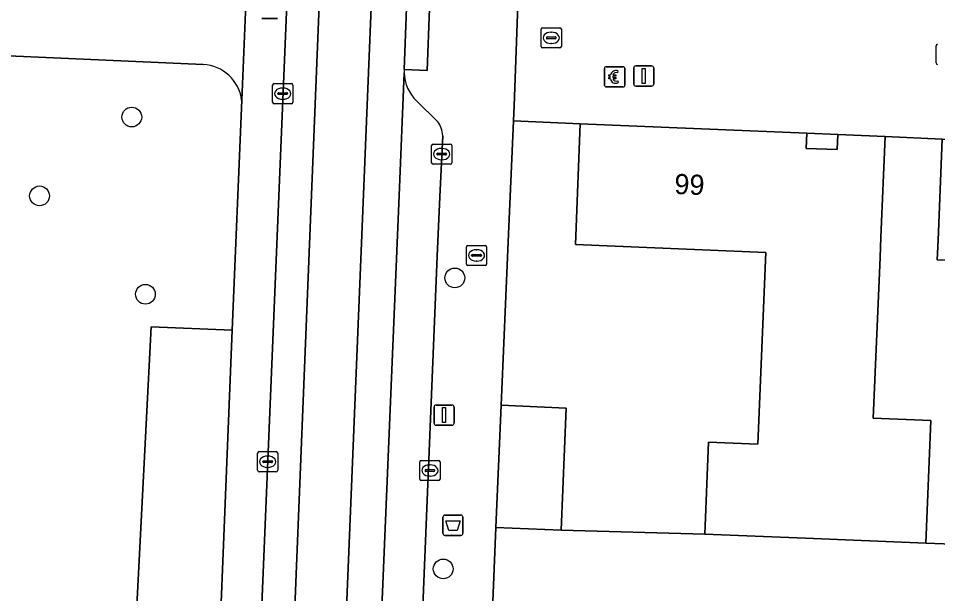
# Model space of a CAD drawing. Extents: x 160786 to 161429, y 386828 to 387485.
# Drawn here: x 161279.33 to 161324.86, y 386925.96 to 386954.48 of the extents above; entities that cross this region are included whole.
import ezdxf

# ---------------------------------------------------------------- set-up
doc = ezdxf.new("R2010")
doc.units = 0
for name, color, linetype in [('IMGEO_Afvalbak', 7, 'Continuous'), ('IMGEO_Betaalautomaat', 7, 'Continuous'), ('IMGEO_Boom', 7, 'Continuous'), ('IMGEO_Brandkraan', 7, 'Continuous'), ('IMGEO_Erf', 7, 'Continuous'), ('IMGEO_Groenvoorziening', 7, 'Continuous'), ('IMGEO_Hek', 7, 'Continuous'), ('IMGEO_Kolk', 7, 'Continuous'), ('IMGEO_Lichtmast', 7, 'Continuous'), ('IMGEO_Muur', 7, 'Continuous'), ('IMGEO_Pand', 7, 'Continuous'), ('IMGEO_Pand_nummerreeks', 7, 'Continuous'), ('IMGEO_Parkeervlak_gesloten', 7, 'Continuous'), ('IMGEO_Rijbaan_lokaal_gesloten', 7, 'Continuous'), ('IMGEO_Rijbaan_lokaal_open', 7, 'Continuous'), ('IMGEO_Voetpad_open', 7, 'Continuous')]:
    doc.layers.add(name, color=color, linetype=linetype)

msp = doc.modelspace()

# ---------------------------------------------------------------- linework, layer by layer
at = {"layer": 'IMGEO_Afvalbak'}
for p, q in [((161300.455, 386929.852), (161301.245, 386929.852)), ((161301.245, 386929.852), (161300.455, 386929.852)), ((161300.355, 386928.952), (161300.355, 386929.752)), ((161300.355, 386929.752), (161300.355, 386928.952)), ((161301.345, 386929.752), (161301.345, 386928.952)), ((161301.345, 386928.952), (161301.345, 386929.752)), ((161301.245, 386928.852), (161300.455, 386928.852)), ((161300.455, 386928.852), (161301.245, 386928.852))]:
    msp.add_line(p, q, dxfattribs=at)
msp.add_lwpolyline([(161300.498, 386929.566), (161301.202, 386929.566), (161301.053, 386929.096), (161300.647, 386929.096), (161300.498, 386929.566)], dxfattribs=at)
for centre, start, end in [((161300.455, 386929.752), 90, 180), ((161300.455, 386929.752), 90, 180), ((161301.245, 386929.752), 0, 90), ((161301.245, 386929.752), 360, 90), ((161300.455, 386928.952), 180, 270), ((161300.455, 386928.952), 180, 270), ((161301.245, 386928.952), 270, 0), ((161301.245, 386928.952), 270, 0)]:
    msp.add_arc(centre, 0.1, start, end, dxfattribs=at)
at = {"layer": 'IMGEO_Betaalautomaat'}
for p, q in [((161308.362, 386951.154), (161308.362, 386951.995)), ((161308.362, 386951.995), (161308.362, 386951.154)), ((161308.437, 386952.078), (161309.278, 386952.078)), ((161309.278, 386952.078), (161308.437, 386952.078)), ((161309.024, 386951.883), (161309.007, 386951.783)), ((161309.361, 386952.004), (161309.361, 386951.163)), ((161309.361, 386951.163), (161309.361, 386952.004)), ((161308.645, 386951.542), (161308.645, 386951.61)), ((161308.766, 386951.61), (161308.766, 386951.542)), ((161309.011, 386951.377), (161309.033, 386951.29)), ((161309.287, 386951.079), (161308.446, 386951.079)), ((161308.446, 386951.079), (161309.287, 386951.079))]:
    msp.add_line(p, q, dxfattribs=at)
for points in [[(161308.645, 386951.61), (161308.576, 386951.61), (161308.576, 386951.679), (161308.655, 386951.679)], [(161308.65, 386951.473), (161308.576, 386951.473), (161308.576, 386951.542), (161308.645, 386951.542)], [(161308.777, 386951.679), (161308.924, 386951.679), (161308.924, 386951.61), (161308.766, 386951.61)], [(161308.766, 386951.542), (161308.924, 386951.542), (161308.924, 386951.473), (161308.78, 386951.473)]]:
    msp.add_lwpolyline(points, dxfattribs=at)
for centre, radius, start, end in [((161308.44, 386952.001), 0.0779, 92.4484, 184.2845), ((161308.44, 386952.001), 0.0779, 92.4484, 184.2845), ((161308.938, 386951.603), 0.293, 73.014, 165.0139), ((161308.944, 386951.616), 0.179, 69.3236, 159.5683), ((161309.284, 386952.001), 0.0779, 2.4484, 94.2845), ((161309.284, 386952.001), 0.0779, 2.4484, 94.2845), ((161308.911, 386951.528), 0.267, 191.8096, 297.0389), ((161308.944, 386951.543), 0.179, 202.7625, 291.8693), ((161308.44, 386951.157), 0.0779, 182.4484, 274.2845), ((161308.44, 386951.157), 0.0779, 182.4484, 274.2845), ((161309.284, 386951.157), 0.0779, 272.4484, 4.2845), ((161309.284, 386951.157), 0.0779, 272.4484, 4.2845)]:
    msp.add_arc(centre, radius, start, end, dxfattribs=at)
at = {"layer": 'IMGEO_Boom'}
for centre in [(161284.944, 386949.587), (161280.373, 386945.679), (161300.945, 386941.612), (161285.619, 386940.8), (161300.368, 386927.189)]:
    msp.add_circle(centre, 0.489, dxfattribs=at)
at = {"layer": 'IMGEO_Brandkraan'}
for p, q in [((161301.519, 386942.3), (161301.519, 386943.152)), ((161301.594, 386943.226), (161302.446, 386943.226)), ((161302.52, 386943.152), (161302.52, 386942.3)), ((161301.778, 386942.72), (161301.778, 386942.732)), ((161302.216, 386942.683), (161301.818, 386942.683)), ((161301.821, 386942.769), (161302.219, 386942.769)), ((161302.007, 386943.006), (161302.032, 386943.006)), ((161302.262, 386942.732), (161302.262, 386942.72)), ((161302.446, 386942.226), (161301.594, 386942.226)), ((161302.03, 386942.446), (161302.005, 386942.446))]:
    msp.add_line(p, q, dxfattribs=at)
for points in [[(161301.519, 386942.3), (161301.519, 386943.152)], [(161301.594, 386943.226), (161302.446, 386943.226)], [(161302.52, 386943.152), (161302.52, 386942.3)], [(161302.446, 386942.226), (161301.594, 386942.226)]]:
    msp.add_lwpolyline(points, dxfattribs=at)
for centre, radius, start, end in [((161301.596, 386943.15), 0.0765, 91.552, 178.448), ((161301.596, 386943.15), 0.0765, 91.552, 178.448), ((161302.444, 386943.15), 0.0765, 1.552, 88.448), ((161302.444, 386943.15), 0.0765, 1.552, 88.448), ((161301.818, 386942.729), 0.0403, 85.8775, 175.7526), ((161301.815, 386942.719), 0.0366, 178.938, 274.7102), ((161302.219, 386942.726), 0.043, 264.8664, 352.4533), ((161302.223, 386942.731), 0.0386, 1.7309, 96.639), ((161301.596, 386942.302), 0.0765, 181.552, 268.448), ((161301.596, 386942.302), 0.0765, 181.552, 268.448), ((161302.444, 386942.302), 0.0765, 271.552, 358.448), ((161302.444, 386942.302), 0.0765, 271.552, 358.448)]:
    msp.add_arc(centre, radius, start, end, dxfattribs=at)
for centre, major_axis, ratio, start_param, end_param in [((161302.006, 386942.726), (-0.387, 0.002), 0.722429, 4.712389, 7.853982), ((161302.031, 386942.726), (-0.39, 0.002), 0.717154, 1.570796, 4.712389)]:
    msp.add_ellipse(centre, major_axis=major_axis, ratio=ratio, start_param=start_param, end_param=end_param, dxfattribs=at)
at = {"layer": 'IMGEO_Erf'}
for points in [[(161303.238, 386935.299), (161306.461, 386935.163), (161306.205, 386929.1), (161313.324, 386928.917), (161313.516, 386933.478), (161315.949, 386933.376), (161316.348, 386942.867), (161306.923, 386943.264), (161307.152, 386949.254), (161303.85, 386949.393), (161303.59, 386943.404)], [(161318.382, 386948.782), (161318.351, 386948.033), (161319.89, 386947.969), (161319.921, 386948.717)], [(161334.304, 386942.104), (161324.836, 386942.502), (161324.878, 386943.488), (161325.088, 386948.483), (161322.258, 386948.619), (161322.048, 386943.624), (161322.006, 386942.621), (161321.671, 386934.657), (161324.526, 386934.537), (161324.27, 386928.456), (161331.342, 386928.203), (161331.53, 386932.684), (161333.904, 386932.585)]]:
    msp.add_lwpolyline(points, close=True, dxfattribs=at)
at = {"layer": 'IMGEO_Groenvoorziening'}
for points in [[(161288.483, 386952.19), (161278.829, 386952.625), (161256.507, 386953.514), (161239.952, 386954.165), (161238.005, 386908.916), (161247.035, 386908.53), (161246.861, 386904.602), (161249.934, 386904.471), (161250.1, 386908.393), (161276.354, 386907.664), (161284.67, 386915.068), (161285.895, 386939.183)], [(161285.895, 386939.183), (161289.921, 386939.02), (161290.386, 386950.426)]]:
    msp.add_lwpolyline(points, dxfattribs=at)
for points in [[(161288.941, 386914.885), (161289.921, 386939.02), (161285.895, 386939.183), (161284.67, 386915.068)], [(161375.253, 386926.43), (161370.258, 386926.64), (161367.184, 386926.77), (161360.13, 386926.991), (161349.258, 386927.448), (161342.263, 386927.744), (161331.342, 386928.203), (161324.27, 386928.456), (161318.32, 386928.707), (161313.324, 386928.917), (161306.205, 386929.1), (161302.982, 386929.236), (161302.493, 386917.433), (161315.258, 386916.897), (161315.473, 386922.033), (161318.102, 386921.923), (161320.34, 386921.824), (161375.065, 386919.394)]]:
    msp.add_lwpolyline(points, close=True, dxfattribs=at)
msp.add_arc((161288.386, 386950.177), 2.015, 7.0993, 87.2423, dxfattribs=at)
at = {"layer": 'IMGEO_Hek'}
msp.add_lwpolyline([(161284.67, 386915.068), (161285.895, 386939.183)], dxfattribs=at)
at = {"layer": 'IMGEO_Kolk'}
for p, q in [((161305.295, 386954.012), (161306.147, 386954.012)), ((161305.22, 386953.086), (161305.22, 386953.938)), ((161305.479, 386953.506), (161305.479, 386953.518)), ((161305.522, 386953.555), (161305.92, 386953.555)), ((161305.708, 386953.792), (161305.733, 386953.792)), ((161305.963, 386953.518), (161305.963, 386953.506)), ((161306.221, 386953.938), (161306.221, 386953.086)), ((161305.917, 386953.469), (161305.519, 386953.469)), ((161305.731, 386953.232), (161305.706, 386953.232)), ((161324.784, 386952.265), (161324.784, 386953.117)), ((161306.147, 386953.012), (161305.295, 386953.012)), ((161291.994, 386951.245), (161292.846, 386951.245)), ((161291.919, 386950.319), (161291.919, 386951.171)), ((161292.221, 386950.788), (161292.619, 386950.788)), ((161292.407, 386951.025), (161292.432, 386951.025)), ((161292.92, 386951.171), (161292.92, 386950.319)), ((161292.178, 386950.739), (161292.178, 386950.751)), ((161292.616, 386950.702), (161292.218, 386950.702)), ((161292.43, 386950.465), (161292.405, 386950.465)), ((161292.662, 386950.751), (161292.662, 386950.739)), ((161292.846, 386950.245), (161291.994, 386950.245)), ((161299.793, 386947.322), (161299.793, 386948.174)), ((161299.868, 386948.248), (161300.72, 386948.248)), ((161300.794, 386948.174), (161300.794, 386947.322)), ((161300.052, 386947.742), (161300.052, 386947.754)), ((161300.49, 386947.705), (161300.092, 386947.705)), ((161300.095, 386947.791), (161300.493, 386947.791)), ((161300.281, 386948.028), (161300.306, 386948.028)), ((161300.536, 386947.754), (161300.536, 386947.742)), ((161300.72, 386947.248), (161299.868, 386947.248)), ((161300.304, 386947.468), (161300.279, 386947.468)), ((161291.173, 386932.076), (161291.173, 386932.928)), ((161291.248, 386933.002), (161292.1, 386933.002)), ((161291.661, 386932.782), (161291.686, 386932.782)), ((161292.174, 386932.928), (161292.174, 386932.076)), ((161299.285, 386932.565), (161300.137, 386932.565)), ((161291.432, 386932.496), (161291.432, 386932.508)), ((161291.87, 386932.459), (161291.472, 386932.459)), ((161291.475, 386932.545), (161291.873, 386932.545)), ((161291.684, 386932.222), (161291.659, 386932.222)), ((161291.916, 386932.508), (161291.916, 386932.496)), ((161299.21, 386931.639), (161299.21, 386932.491)), ((161299.698, 386932.345), (161299.723, 386932.345)), ((161300.211, 386932.491), (161300.211, 386931.639)), ((161292.1, 386932.002), (161291.248, 386932.002)), ((161299.469, 386932.059), (161299.469, 386932.071)), ((161299.907, 386932.022), (161299.509, 386932.022)), ((161299.512, 386932.108), (161299.91, 386932.108)), ((161299.721, 386931.785), (161299.696, 386931.785)), ((161299.953, 386932.071), (161299.953, 386932.059)), ((161300.137, 386931.565), (161299.285, 386931.565))]:
    msp.add_line(p, q, dxfattribs=at)
for points in [[(161305.295, 386954.012), (161306.147, 386954.012)], [(161305.22, 386953.086), (161305.22, 386953.938)], [(161306.221, 386953.938), (161306.221, 386953.086)], [(161324.784, 386952.265), (161324.784, 386953.117)], [(161306.147, 386953.012), (161305.295, 386953.012)], [(161291.994, 386951.245), (161292.846, 386951.245)], [(161291.919, 386950.319), (161291.919, 386951.171)], [(161292.92, 386951.171), (161292.92, 386950.319)], [(161292.846, 386950.245), (161291.994, 386950.245)], [(161299.793, 386947.322), (161299.793, 386948.174)], [(161299.868, 386948.248), (161300.72, 386948.248)], [(161300.794, 386948.174), (161300.794, 386947.322)], [(161300.72, 386947.248), (161299.868, 386947.248)], [(161291.173, 386932.076), (161291.173, 386932.928)], [(161291.248, 386933.002), (161292.1, 386933.002)], [(161292.174, 386932.928), (161292.174, 386932.076)], [(161299.285, 386932.565), (161300.137, 386932.565)], [(161299.21, 386931.639), (161299.21, 386932.491)], [(161300.211, 386932.491), (161300.211, 386931.639)], [(161292.1, 386932.002), (161291.248, 386932.002)], [(161300.137, 386931.565), (161299.285, 386931.565)]]:
    msp.add_lwpolyline(points, dxfattribs=at)
for centre, radius, start, end in [((161305.297, 386953.936), 0.0765, 91.552, 178.448), ((161305.297, 386953.936), 0.0765, 91.552, 178.448), ((161306.145, 386953.936), 0.0765, 1.552, 88.448), ((161306.145, 386953.936), 0.0765, 1.552, 88.448), ((161305.519, 386953.515), 0.0403, 85.8775, 175.7526), ((161305.924, 386953.517), 0.0386, 1.7309, 96.639), ((161305.297, 386953.088), 0.0765, 181.552, 268.448), ((161305.297, 386953.088), 0.0765, 181.552, 268.448), ((161305.516, 386953.505), 0.0366, 178.938, 274.7102), ((161305.92, 386953.512), 0.043, 264.8664, 352.4533), ((161306.145, 386953.088), 0.0765, 271.552, 358.448), ((161306.145, 386953.088), 0.0765, 271.552, 358.448), ((161324.861, 386953.115), 0.0765, 91.552, 178.448), ((161324.861, 386953.115), 0.0765, 91.552, 178.448), ((161324.861, 386952.267), 0.0765, 181.552, 268.448), ((161324.861, 386952.267), 0.0765, 181.552, 268.448), ((161291.996, 386951.169), 0.0765, 91.552, 178.448), ((161291.996, 386951.169), 0.0765, 91.552, 178.448), ((161292.844, 386951.169), 0.0765, 1.552, 88.448), ((161292.844, 386951.169), 0.0765, 1.552, 88.448), ((161292.218, 386950.748), 0.0403, 85.8775, 175.7526), ((161292.623, 386950.75), 0.0386, 1.7309, 96.639), ((161292.215, 386950.738), 0.0366, 178.938, 274.7102), ((161292.619, 386950.745), 0.043, 264.8664, 352.4533), ((161291.996, 386950.321), 0.0765, 181.552, 268.448), ((161291.996, 386950.321), 0.0765, 181.552, 268.448), ((161292.844, 386950.321), 0.0765, 271.552, 358.448), ((161292.844, 386950.321), 0.0765, 271.552, 358.448), ((161299.87, 386948.172), 0.0765, 91.552, 178.448), ((161299.87, 386948.172), 0.0765, 91.552, 178.448), ((161300.718, 386948.172), 0.0765, 1.552, 88.448), ((161300.718, 386948.172), 0.0765, 1.552, 88.448), ((161300.092, 386947.751), 0.0403, 85.8775, 175.7526), ((161300.089, 386947.741), 0.0366, 178.938, 274.7102), ((161300.493, 386947.748), 0.043, 264.8664, 352.4533), ((161300.497, 386947.753), 0.0386, 1.7309, 96.639), ((161299.87, 386947.324), 0.0765, 181.552, 268.448), ((161299.87, 386947.324), 0.0765, 181.552, 268.448), ((161300.718, 386947.324), 0.0765, 271.552, 358.448), ((161300.718, 386947.324), 0.0765, 271.552, 358.448), ((161291.25, 386932.926), 0.0765, 91.552, 178.448), ((161291.25, 386932.926), 0.0765, 91.552, 178.448), ((161292.098, 386932.926), 0.0765, 1.552, 88.448), ((161292.098, 386932.926), 0.0765, 1.552, 88.448), ((161299.287, 386932.489), 0.0765, 91.552, 178.448), ((161299.287, 386932.489), 0.0765, 91.552, 178.448), ((161300.135, 386932.489), 0.0765, 1.552, 88.448), ((161300.135, 386932.489), 0.0765, 1.552, 88.448), ((161291.472, 386932.505), 0.0403, 85.8775, 175.7526), ((161291.469, 386932.495), 0.0366, 178.938, 274.7102), ((161291.873, 386932.502), 0.043, 264.8664, 352.4533), ((161291.877, 386932.507), 0.0386, 1.7309, 96.639), ((161291.25, 386932.078), 0.0765, 181.552, 268.448), ((161291.25, 386932.078), 0.0765, 181.552, 268.448), ((161292.098, 386932.078), 0.0765, 271.552, 358.448), ((161292.098, 386932.078), 0.0765, 271.552, 358.448), ((161299.509, 386932.068), 0.0403, 85.8775, 175.7526), ((161299.506, 386932.058), 0.0366, 178.938, 274.7102), ((161299.91, 386932.065), 0.043, 264.8664, 352.4533), ((161299.914, 386932.07), 0.0386, 1.7309, 96.639), ((161299.287, 386931.641), 0.0765, 181.552, 268.448), ((161299.287, 386931.641), 0.0765, 181.552, 268.448), ((161300.135, 386931.641), 0.0765, 271.552, 358.448), ((161300.135, 386931.641), 0.0765, 271.552, 358.448)]:
    msp.add_arc(centre, radius, start, end, dxfattribs=at)
for centre, major_axis, ratio, start_param, end_param in [((161305.707, 386953.512), (-0.387, 0.002), 0.722429, 4.712389, 7.853982), ((161305.732, 386953.512), (-0.39, 0.002), 0.717154, 1.570796, 4.712389), ((161292.406, 386950.745), (-0.387, 0.002), 0.722429, 4.712389, 7.853982), ((161292.431, 386950.745), (-0.39, 0.002), 0.717154, 1.570796, 4.712389), ((161300.28, 386947.748), (-0.387, 0.002), 0.722429, 4.712389, 7.853982), ((161300.305, 386947.748), (-0.39, 0.002), 0.717154, 1.570796, 4.712389), ((161291.66, 386932.502), (-0.387, 0.002), 0.722429, 4.712389, 7.853982), ((161291.685, 386932.502), (-0.39, 0.002), 0.717154, 1.570796, 4.712389), ((161299.697, 386932.065), (-0.387, 0.002), 0.722429, 4.712389, 7.853982), ((161299.722, 386932.065), (-0.39, 0.002), 0.717154, 1.570796, 4.712389)]:
    msp.add_ellipse(centre, major_axis=major_axis, ratio=ratio, start_param=start_param, end_param=end_param, dxfattribs=at)
at = {"layer": 'IMGEO_Lichtmast'}
for p, q in [((161292.168, 386954.476), (161291.378, 386954.476)), ((161291.378, 386954.476), (161292.168, 386954.476)), ((161309.804, 386951.221), (161309.804, 386952.021)), ((161309.804, 386952.021), (161309.804, 386951.221)), ((161309.904, 386952.121), (161310.694, 386952.121)), ((161310.694, 386952.121), (161309.904, 386952.121)), ((161310.794, 386952.021), (161310.794, 386951.221)), ((161310.794, 386951.221), (161310.794, 386952.021)), ((161310.694, 386951.121), (161309.904, 386951.121)), ((161309.904, 386951.121), (161310.694, 386951.121)), ((161300.014, 386935.312), (161300.804, 386935.312)), ((161300.804, 386935.312), (161300.014, 386935.312)), ((161299.914, 386934.412), (161299.914, 386935.212)), ((161299.914, 386935.212), (161299.914, 386934.412)), ((161300.904, 386935.212), (161300.904, 386934.412)), ((161300.904, 386934.412), (161300.904, 386935.212)), ((161300.804, 386934.312), (161300.014, 386934.312)), ((161300.014, 386934.312), (161300.804, 386934.312))]:
    msp.add_line(p, q, dxfattribs=at)
for points in [[(161310.224, 386951.996), (161310.374, 386951.996), (161310.374, 386951.246), (161310.224, 386951.246), (161310.224, 386951.996)], [(161300.334, 386935.187), (161300.484, 386935.187), (161300.484, 386934.437), (161300.334, 386934.437), (161300.334, 386935.187)]]:
    msp.add_lwpolyline(points, dxfattribs=at)
for centre, start, end in [((161309.904, 386952.021), 90, 180), ((161309.904, 386952.021), 90, 180), ((161310.694, 386952.021), 0, 90), ((161310.694, 386952.021), 360, 90), ((161309.904, 386951.221), 180, 270), ((161309.904, 386951.221), 180, 270), ((161310.694, 386951.221), 270, 0), ((161310.694, 386951.221), 270, 0), ((161300.014, 386935.212), 90, 180), ((161300.014, 386935.212), 90, 180), ((161300.804, 386935.212), 0, 90), ((161300.804, 386935.212), 360, 90), ((161300.014, 386934.412), 180, 270), ((161300.014, 386934.412), 180, 270), ((161300.804, 386934.412), 270, 0), ((161300.804, 386934.412), 270, 0)]:
    msp.add_arc(centre, 0.1, start, end, dxfattribs=at)
at = {"layer": 'IMGEO_Muur'}
msp.add_lwpolyline([(161303.59, 386943.404), (161303.238, 386935.299)], dxfattribs=at)
at = {"layer": 'IMGEO_Pand'}
for points in [[(161307.152, 386949.254), (161306.923, 386943.264), (161316.348, 386942.867), (161315.949, 386933.376), (161313.516, 386933.478), (161313.324, 386928.917), (161318.32, 386928.707), (161324.27, 386928.456), (161324.526, 386934.537), (161321.671, 386934.657), (161322.006, 386942.621), (161322.048, 386943.624), (161322.258, 386948.619), (161319.921, 386948.717), (161319.89, 386947.969), (161318.351, 386948.033), (161318.382, 386948.782)], [(161325.088, 386948.483), (161324.878, 386943.488), (161324.836, 386942.502), (161334.304, 386942.104), (161333.904, 386932.585), (161331.53, 386932.684), (161331.342, 386928.203), (161342.263, 386927.744), (161342.517, 386933.765), (161339.507, 386933.892), (161339.843, 386941.882), (161339.884, 386942.857), (161340.094, 386947.852), (161337.757, 386947.95), (161337.726, 386947.202), (161336.187, 386947.266), (161336.218, 386948.015)], [(161302.982, 386929.236), (161306.205, 386929.1), (161306.461, 386935.163), (161303.238, 386935.299)]]:
    msp.add_lwpolyline(points, close=True, dxfattribs=at)
at = {"layer": 'IMGEO_Parkeervlak_gesloten'}
for points in [[(161298.439, 386951.784), (161298.179, 386945.692), (161296.461, 386904.443)], [(161300.099, 386949.355), (161299.044, 386950.382)], [(161300.066, 386942.692), (161300.203, 386945.628), (161300.345, 386948.662)], [(161298.617, 386907.135), (161298.664, 386908.404), (161300.066, 386942.692)]]:
    msp.add_lwpolyline(points, dxfattribs=at)
for centre, radius, start, end in [((161300.483, 386951.834), 2.044, 181.4128, 225.2702), ((161299.073, 386948.601), 1.273, 2.7573, 36.3303)]:
    msp.add_arc(centre, radius, start, end, dxfattribs=at)
at = {"layer": 'IMGEO_Rijbaan_lokaal_gesloten'}
for points in [[(161295.615, 386998.468), (161296.227, 387004.228), (161298.285, 387055.038), (161296.641, 387055.12), (161296.047, 387040.014), (161295.788, 387033.414), (161294.936, 387011.744), (161294.673, 387005.041), (161294.475, 387000), (161293.996, 386989.734), (161293.806, 386983.797), (161290.641, 386907.552)], [(161294.661, 386902.681), (161299.353, 387017.413), (161300.938, 387054.844), (161298.285, 387055.038), (161296.227, 387004.228), (161295.615, 386998.468)], [(161298.691, 386958.606), (161298.922, 386964.506), (161300.177, 386996.031), (161300.266, 386998.149), (161301.03, 387016.276), (161301.348, 387024.011), (161301.576, 387029.9), (161301.584, 387030.091), (161301.604, 387030.255), (161301.823, 387036.16), (161302.586, 387054.794), (161300.938, 387054.844), (161299.353, 387017.413), (161294.661, 386902.681)], [(161292.315, 386907.717), (161295.632, 386989.894), (161295.454, 386994.199)], [(161295.454, 386994.199), (161295.632, 386989.894), (161292.315, 386907.717)], [(161298.441, 386951.94), (161298.669, 386958.063)], [(161296.461, 386904.443), (161298.179, 386945.692), (161298.439, 386951.784)]]:
    msp.add_lwpolyline(points, dxfattribs=at)
msp.add_arc((161299.96, 386951.843), 1.522, 176.3284, 182.2026, dxfattribs=at)
at = {"layer": 'IMGEO_Rijbaan_lokaal_open'}
msp.add_lwpolyline([(161323.794, 386956.846), (161304.173, 386957.768), (161304.054, 386954.684), (161303.879, 386950.146), (161303.85, 386949.393), (161307.152, 386949.254), (161318.382, 386948.782), (161319.921, 386948.717), (161322.258, 386948.619), (161325.088, 386948.483), (161336.218, 386948.015), (161337.757, 386947.95), (161340.094, 386947.852), (161343.018, 386947.75), (161354.204, 386947.279), (161355.743, 386947.214), (161358.08, 386947.116), (161361.02, 386947.066), (161370.046, 386946.686), (161370.161, 386949.634), (161370.282, 386952.721), (161370.403, 386955.808)], dxfattribs=at)
at = {"layer": 'IMGEO_Voetpad_open'}
for points in [[(161293.806, 386983.797), (161291.727, 386983.944), (161291.591, 386981.225), (161290.663, 386957.219), (161290.668, 386957.173), (161290.386, 386950.426), (161289.921, 386939.02), (161288.941, 386914.885), (161288.581, 386906.034), (161288.788, 386902.201), (161289.271, 386902.937), (161289.686, 386903.713), (161290.03, 386904.523), (161290.3, 386905.361), (161290.494, 386906.22), (161290.611, 386907.092), (161290.641, 386907.552)], [(161298.441, 386951.94), (161299.575, 386951.886), (161299.805, 386958.056), (161298.669, 386958.063)]]:
    msp.add_lwpolyline(points, close=True, dxfattribs=at)
for points in [[(161152.89, 386957.853), (161156.191, 386957.722), (161190.749, 386956.141), (161213.54, 386955.235), (161233.098, 386954.435), (161234.795, 386954.368), (161237.237, 386954.272), (161239.952, 386954.165), (161256.507, 386953.514), (161278.829, 386952.625), (161288.483, 386952.19)], [(161302.493, 386917.433), (161302.982, 386929.236), (161303.238, 386935.299), (161303.59, 386943.404), (161303.85, 386949.393), (161303.879, 386950.146), (161304.054, 386954.684), (161304.173, 386957.768), (161299.805, 386958.056), (161299.575, 386951.886), (161298.441, 386951.94)], [(161290.386, 386950.426), (161290.668, 386957.173), (161290.663, 386957.219)], [(161299.044, 386950.382), (161300.099, 386949.355)], [(161300.345, 386948.662), (161300.203, 386945.628), (161300.066, 386942.692), (161298.664, 386908.404), (161298.617, 386907.135)]]:
    msp.add_lwpolyline(points, dxfattribs=at)
for centre, radius, start, end in [((161288.386, 386950.177), 2.015, 7.0993, 87.2423), ((161299.96, 386951.843), 1.522, 176.3284, 182.2026), ((161300.483, 386951.834), 2.044, 181.4128, 225.2702), ((161299.073, 386948.601), 1.273, 2.7573, 36.3303)]:
    msp.add_arc(centre, radius, start, end, dxfattribs=at)

# ---------------------------------------------------------------- texts
at = {"layer": 'IMGEO_Pand_nummerreeks'}
msp.add_text('99', height=1, rotation=357.5933, dxfattribs=at).set_placement((161311.804, 386945.776))

doc.saveas('drawing.dxf')
